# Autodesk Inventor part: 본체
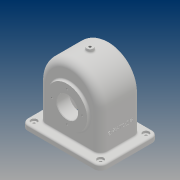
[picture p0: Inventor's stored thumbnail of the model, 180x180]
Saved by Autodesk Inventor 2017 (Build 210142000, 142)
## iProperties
Part Number: 본체
Material: 일반
Document SubType Name: Modeling
Designer: 20
Density: 1 g/cm^3
Appearance: 기본값
Author: 20
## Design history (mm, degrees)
sketch "스케치1"
  geometry: L1 (58, 0)-(58, -78); L2 (58, -78)-(-58, -78); L3 (-58, -78)-(-58, 0); A1 r 58 centre (0, 0) between (58, 0) and (-58, 0); 1 further point
  constraints: 6 end point, 2 point on circle, 2 tangent, 2 vertical, 1 centre point, 1 coincident, 1 horizontal
  dimensions: "d0" = 116 diameter of A1; "d1" = 78 distance from line of L2 point (0, 0)
extrude "돌출1" new body sketch "스케치1" stored distance "d2" = 77; taper "d3" = 0 deg
sketch "스케치3"
  geometry: L1 (52, 3.665)-(52, -78); L2 (52, -78)-(-52, -78); L3 (-52, -78)-(-52, 0); A1 r 52 centre (0, 0) between (52, 0) and (-52, 0); A2 r 58 centre (0, 0) between (58, 0) and (-58, 0) reference; 1 further point
  constraints: 6 end point, 2 point on circle, 2 tangent, 2 vertical, 1 centre point, 1 concentric, 1 horizontal, 1 point on line
  dimensions: "d8" = 104 diameter of A1; "d9" = 78 distance from line of L2 point (0, 0)
extrude "돌출3" cut sketch "스케치3" stored distance "d10" = 67; taper "d11" = 0 deg
sketch "스케치4"
  geometry: L1 (-58, -78)-(58, -78) reference; C1 r 38 at (0, -13); 1 further point
  constraints: 1 centre point, 1 vertical alignment
  dimensions: "d12" = 76 diameter of C1; "d13" = 65 distance from line of L1 C1.centre
extrude "돌출4" join sketch "스케치4" distance "d14" = 5; taper "d15" = 0 deg
sketch "스케치5"
  geometry: L1 (-58, 78)-(58, 78) reference; C1 r 28 at (0, 13); 1 further point
  constraints: 1 centre point, 1 vertical alignment
  dimensions: "d16" = 56 diameter of C1; "d17" = 65 distance from line of L1 C1.centre
extrude "돌출5" join sketch "스케치5" distance "d18" = 14; taper "d19" = 0 deg
feature "면 기울기1" dims angle "d20" = 40 deg
sketch "스케치6"
  geometry: L1 (58, 78)-(-58, 78) reference; C1 r 38 at (0, 13); 1 further point
  constraints: 1 centre point, 1 vertical alignment
  dimensions: "d21" = 76 diameter of C1; "d22" = 65 distance from line of L1 C1.centre
extrude "돌출6" join sketch "스케치6" distance "d23" = 10; taper "d24" = 0 deg
sketch "스케치7"
  geometry: C1 r 20 at (0, 0); C2 r 38 at (0, 0) reference; 1 further point
  constraints: 1 centre point, 1 concentric
  dimensions: "d25" = 40 diameter of C1
extrude "돌출7" cut sketch "스케치7" stored distance "d26" = 10; taper "d27" = 0 deg
sketch "스케치8"
  geometry: L1 (-17, -93.5)-(133, -93.5); L2 (133, -93.5)-(133, 16.5); L3 (133, 16.5)-(-17, 16.5); L4 (-17, 16.5)-(-17, -93.5); L5 (-17, -93.5)-(133, 16.5); L6 (133, -93.5)-(-17, 16.5); L7 (0, 0)-(116, 0) reference; L8 (0, 0)-(0, -77) reference; L9 (116, -77)-(0, -77) reference; L10 (116, 0)-(116, -77) reference; 1 further point
  constraints: 12 end point, 2 midpoint, 2 parallel, 1 horizontal, 1 perpendicular
  dimensions: "d28" = 150 distance of L2.end L3.end; "d29" = 110 distance of L3.end L1.start
extrude "돌출8" join sketch "스케치8" distance "d30" = 10; taper "d31" = 0 deg
node "작업 평면1"
sketch "스케치9"
  geometry: C1 r 6 at (75, 55); 1 further point
  constraints: 1 centre point, 1 coincident
  dimensions: "d33" = 12 diameter of C1
extrude "돌출9" join sketch "스케치9" distance "d34" = 10; taper "d35" = 5 deg
fillet "모깎기1" dims "d36" = 12
hole "구멍1" diameter "d39" = 5; stored, may be unused: countersink angle "d43" = 90 deg, drill point angle "d45" = 118 deg; dims "d37" = 10, "d38" = 10, "d40" = 6.35, "d41" = 12, "d42" = 4, "d44" = 9.525
hole "구멍2" diameter "d48" = 5; stored, may be unused: countersink angle "d52" = 90 deg, drill point angle "d54" = 118 deg; dims "d46" = 10, "d47" = 10, "d49" = 6.35, "d50" = 12, "d51" = 4, "d53" = 9.525
hole "구멍3" diameter "d57" = 5; stored, may be unused: countersink angle "d61" = 90 deg, drill point angle "d63" = 118 deg; dims "d55" = 10, "d56" = 10, "d58" = 6.35, "d59" = 12, "d60" = 4, "d62" = 9.525
hole "구멍4" diameter "d66" = 5; stored, may be unused: countersink angle "d70" = 90 deg, drill point angle "d72" = 118 deg; dims "d64" = 10, "d65" = 10, "d67" = 6.35, "d68" = 12, "d69" = 4, "d71" = 9.525
sketch "스케치10" dims "d73" = 58
  geometry: C1 r 38 at (0, 0) reference; 3 further points
  constraints: 2 vertical alignment, 3 other
hole "구멍5" sketch "스케치10" at (0, 29) diameter "d74" = 3.242; stored, may be unused: countersink angle "d78" = 90 deg, drill point angle "d80" = 118 deg; dims "d75" = 8, "d76" = 12, "d77" = 4, "d79" = 10
sketch "스케치11" dims "d84" = 58
  geometry: C1 r 38 at (0, 0) reference; 3 further points
  constraints: 2 vertical alignment, 3 other
hole "구멍6" sketch "스케치11" at (0, -29) diameter "d85" = 3.242; stored, may be unused: countersink angle "d89" = 90 deg, drill point angle "d91" = 118 deg; dims "d86" = 8, "d87" = 12, "d88" = 4, "d90" = 10
fillet "모깎기2" dims "d95" = 13
fillet "모깎기3" dims "d96" = 8
fillet "모깎기4" dims "d97" = 3
fillet "모깎기5" dims "d98" = 3
fillet "모깎기6" dims "d99" = 3
fillet "모깎기7" dims "d100" = 3
chamfer "모따기1" distance "d101" = 1; stored, may be unused: second distance "d102" = 2, angle "d103" = 45 deg
hole "구멍7" diameter "d106" = 4.459; stored, may be unused: countersink angle "d110" = 90 deg, drill point angle "d112" = 118 deg; dims "d104" = 10, "d105" = 10, "d107" = 30, "d108" = 12, "d109" = 4, "d111" = 12.8
sketch "스케치12"
  geometry: L1 (0, -13)-(65, -13) reference; L2 (78, 68.5)-(78, -17.5) reference; 2 further points
  constraints: 1 other
  dimensions: "d113" = 38.5 distance from line of point (38, 25.5) L1; "d114" = 40 distance from line of L2 point (38, 25.5)
feature "엠보싱1" sketch "스케치12" dims "d115" = 0.5, "d116" = 0
fillet "모깎기8" dims "d117" = 3
node "솔리드1"
pattern_circular "원형 패턴1" dims angle "d82" = 360 deg
pattern_circular "원형 패턴2" dims angle "d93" = 360 deg
other parameters: "d32" = -142
